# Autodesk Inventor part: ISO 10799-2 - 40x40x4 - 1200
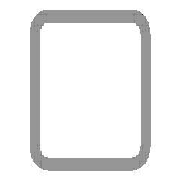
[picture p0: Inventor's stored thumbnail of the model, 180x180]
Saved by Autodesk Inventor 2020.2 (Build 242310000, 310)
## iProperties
Created: 2020-01
Part Number: ISO 10799-2 - 40x40x4 - 1200
Material: Steel, Mild
Description: Structural steels - Cold-formed, welded, structural hollow sections
Document SubType Name: Modeling
Standard: ISO
Designer: thira
Standard Revision: First edition 2011-09-15
Standards Organization: ISO
Language: en-US
Size Designation: 40x40x4
Categories: <MemberInstance><Categories><Category DisplayName="Structural Shapes" InternalName="089c4875-fa83-4c05-b084-43b9cc11f5ed" Mnemonic="GRDR"><CategoryParameter Dis
Stock Number: 40x40x4
Density: 7.85 g/cm^3
Appearance: Semi-Polished
_CCFamilyMember: 11
_CCFamilyDisplayName: ISO 10799-2 (Square) - Structural steels - Cold-formed, welded, structural hollow sections
_FrameMemberDoc: Frame Member File
_Version: 15.0.0
_GetPNFromCC: 1
G_L: 1200.000 mm
G_W: 40.000 mm
G_H: 40.000 mm
IsCustomPart: 1
Author: thira
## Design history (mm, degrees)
node "Start Plane"
node "End Plane"
sketch "Sketch"
  geometry: L1 (-20, -12)-(-20, 12); L2 (-12, 20)-(12, 20); L3 (20, 12)-(20, -12); L4 (12, -20)-(-12, -20); L5 (-12, 16)-(12, 16); L6 (16, 12)-(16, -12); L7 (12, -16)-(-12, -16); L8 (-16, -12)-(-16, 12); L9 (0, 30.32)-(0, -30.32) reference; L10 (-30.32, 0)-(30.32, 0) reference; A1 r 8 centre (-12, -12) between (-20, -12) and (-12, -20); A2 r 8 centre (12, 12) between (20, 12) and (12, 20); A3 r 8 centre (-12, 12) between (-12, 20) and (-20, 12); A4 r 8 centre (12, -12) between (12, -20) and (20, -12); A5 r 4 centre (-12, 12) between (-12, 16) and (-16, 12); A6 r 4 centre (12, 12) between (16, 12) and (12, 16); A7 r 4 centre (12, -12) between (12, -16) and (16, -12); A8 r 4 centre (-12, -12) between (-16, -12) and (-12, -16)
  constraints: 16 end point, 16 point on circle, 8 centre point, 8 tangent, 4 parallel, 3 equal radius, 2 perpendicular, 7 other
  dimensions: "d7" = 8 radius of A1 (= G_IR); "d9" = 40 distance between parallel lines of L1 L3 (= G_W); "d11" = 40 distance between parallel lines of L2 L4 (= G_H); "d12" = 4 distance between parallel lines of L3 L6 (= G_T); "d15" = 20 distance between parallel lines of L9 L3 (= 0.5 x d9); "d16" = 20 distance between parallel lines of L2 L10 (= 0.5 x d11)
extrude "Body" new body sketch "Sketch" stored distance "d3" = 1200 (= G_L); taper "d4" = 0 deg
node "Driven Length"
  sketch "Sketch3"
    geometry: L1 (0, 0)-(10, 0) reference
    constraints: 2 end point, 1 horizontal
  workplane "Work Plane3"
  sketch "Sketch4"
    geometry: L1 (-2, 0)-(12, 0) reference; L2 (-2, 1200)-(12, 1200) reference
    dimensions: "d18" = 1200 distance between parallel lines of L1 L2 (derived)
body "Solid1"
other parameters: "G_W" = 40 [user parameter; used in 1 equation term], "G_H" = 40 [user parameter; used in 1 equation term], "G_T" = 4 [user parameter; used in 1 equation term], "G_IR" = 8 [user parameter; used in 1 equation term], "G_L" = 1200 (= d18) [user parameter; used in 1 equation term], "G_OFFSET_START" = 0 [user parameter; used in 1 equation term], "G_OFFSET_END" = 0 [user parameter; used in 1 equation term], "d13" = 0 (computed from G_OFFSET_START), "d17" = 90 deg, "MAS" = 0.42 [user parameter]
